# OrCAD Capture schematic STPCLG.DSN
size A
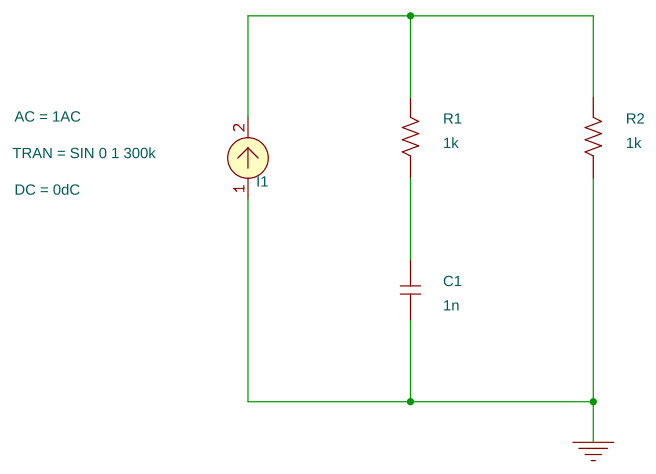
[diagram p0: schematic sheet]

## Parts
C1  1n  [RAD/CK05]
I1  ISRC
R1  1k  [AX/RC05]
R2  1k  [AX/RC05]

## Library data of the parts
C1 = C
I1 = ISRC: AC: 1AC; DC: 0dC; TRAN: SIN 0 1 300k
R1 R2 = R

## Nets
0: C1.1 I1.1(+) R2.1
N00115: I1.2(-) R1.2 R2.2
N00156: C1.2 R1.1
